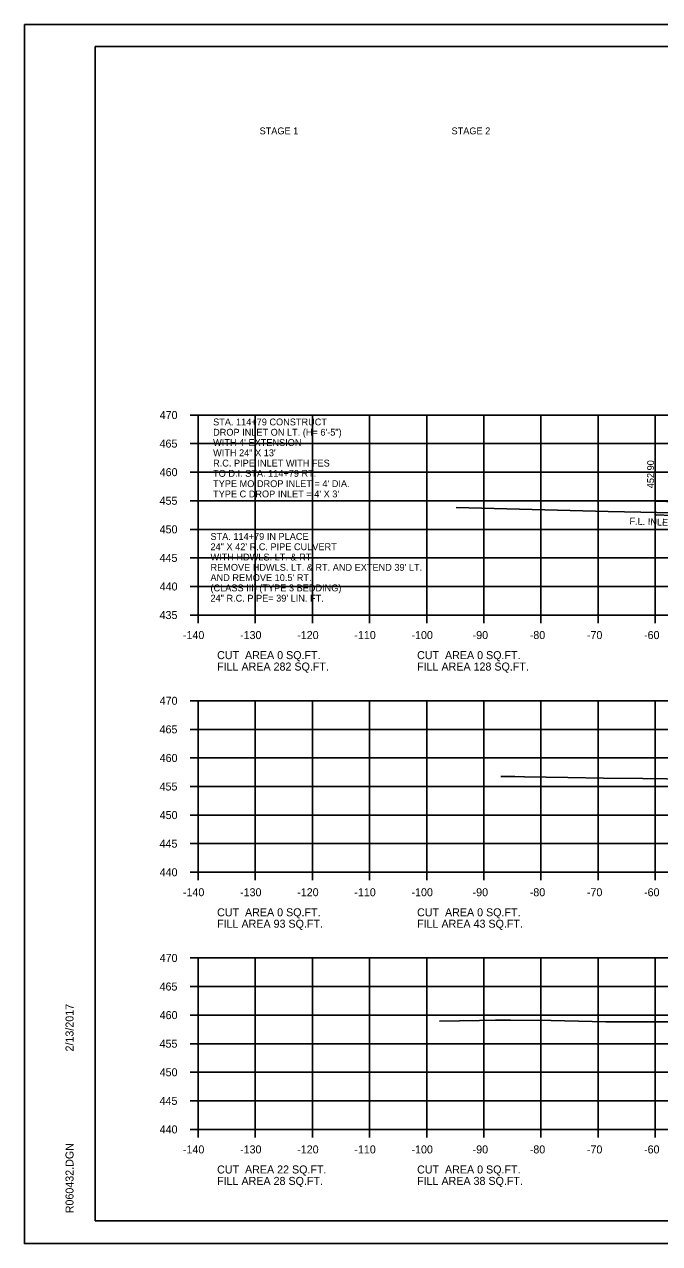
# Model space of a CAD drawing. Extents: x 1538688 to 1540766, y 656250 to 671912.
# Drawn here: x 1538687.8 to 1538798.9, y 658471.3 to 658684.6 of the extents above; entities that cross this region are included whole.
import ezdxf

# ---------------------------------------------------------------- set-up
doc = ezdxf.new("R2010")
doc.units = 0
for name, color, linetype in [('18', 7, 'Continuous'), ('22', 7, 'Continuous'), ('26', 7, 'Continuous'), ('40', 7, 'Continuous'), ('41', 7, 'Continuous'), ('Borings', 7, 'Continuous'), ('Default', 7, 'Continuous'), ('Horizontal Alignment', 7, 'Continuous'), ('RipRap', 7, 'Continuous')]:
    doc.layers.add(name, color=color, linetype=linetype)

msp = doc.modelspace()

# ---------------------------------------------------------------- linework, layer by layer
at = {"layer": '18'}
for points in [[(1538763.34, 658600.06), (1538789.92, 658599.36), (1538815.53, 658598.84)], [(1538771.17, 658553), (1538773.59, 658553.01), (1538775.27, 658552.94), (1538782.89, 658552.83), (1538789.15, 658552.74), (1538795.98, 658552.64), (1538804.31, 658552.52)], [(1538760.4, 658510.18), (1538767.42, 658510.32), (1538770.22, 658510.4), (1538771.41, 658510.38), (1538772.82, 658510.38), (1538779.98, 658510.31), (1538789.55, 658510.1), (1538793.35, 658510.1), (1538804.24, 658510.09)]]:
    msp.add_lwpolyline(points, dxfattribs=at)
at = {"layer": '22'}
for p, q in [((1538718.18, 658616.26), (1538998.18, 658616.26)), ((1538718.18, 658581.26), (1538718.18, 658616.26)), ((1538728.18, 658581.26), (1538728.18, 658616.26)), ((1538738.18, 658581.26), (1538738.18, 658616.26)), ((1538748.18, 658581.26), (1538748.18, 658616.26)), ((1538758.18, 658581.26), (1538758.18, 658616.26)), ((1538768.18, 658581.26), (1538768.18, 658616.26)), ((1538778.18, 658581.26), (1538778.18, 658616.26)), ((1538788.18, 658581.26), (1538788.18, 658616.26)), ((1538798.18, 658581.26), (1538798.18, 658616.26)), ((1538718.18, 658611.26), (1538998.18, 658611.26)), ((1538718.18, 658606.26), (1538998.18, 658606.26)), ((1538718.18, 658601.26), (1538998.18, 658601.26)), ((1538718.18, 658596.26), (1538998.18, 658596.26)), ((1538718.18, 658591.26), (1538998.18, 658591.26)), ((1538718.18, 658586.26), (1538998.18, 658586.26)), ((1538718.18, 658581.26), (1538998.18, 658581.26)), ((1538718.18, 658566.26), (1538998.18, 658566.26)), ((1538718.18, 658536.26), (1538718.18, 658566.26)), ((1538728.18, 658536.26), (1538728.18, 658566.26)), ((1538738.18, 658536.26), (1538738.18, 658566.26)), ((1538748.18, 658536.26), (1538748.18, 658566.26)), ((1538758.18, 658536.26), (1538758.18, 658566.26)), ((1538768.18, 658536.26), (1538768.18, 658566.26)), ((1538778.18, 658536.26), (1538778.18, 658566.26)), ((1538788.18, 658536.26), (1538788.18, 658566.26)), ((1538798.18, 658536.26), (1538798.18, 658566.26)), ((1538718.18, 658561.26), (1538998.18, 658561.26)), ((1538718.18, 658556.26), (1538998.18, 658556.26)), ((1538718.18, 658551.26), (1538998.18, 658551.26)), ((1538718.18, 658546.26), (1538998.18, 658546.26)), ((1538718.18, 658541.26), (1538998.18, 658541.26)), ((1538718.18, 658536.26), (1538998.18, 658536.26)), ((1538718.18, 658521.26), (1538998.18, 658521.26)), ((1538718.18, 658491.26), (1538718.18, 658521.26)), ((1538728.18, 658491.26), (1538728.18, 658521.26)), ((1538738.18, 658491.26), (1538738.18, 658521.26)), ((1538748.18, 658491.26), (1538748.18, 658521.26)), ((1538758.18, 658491.26), (1538758.18, 658521.26)), ((1538768.18, 658491.26), (1538768.18, 658521.26)), ((1538778.18, 658491.26), (1538778.18, 658521.26)), ((1538788.18, 658491.26), (1538788.18, 658521.26)), ((1538798.18, 658491.26), (1538798.18, 658521.26)), ((1538718.18, 658516.26), (1538998.18, 658516.26)), ((1538718.18, 658511.26), (1538998.18, 658511.26)), ((1538718.18, 658506.26), (1538998.18, 658506.26)), ((1538718.18, 658501.26), (1538998.18, 658501.26)), ((1538718.18, 658496.26), (1538998.18, 658496.26)), ((1538718.18, 658491.26), (1538998.18, 658491.26))]:
    msp.add_line(p, q, dxfattribs=at)
at = {"layer": '26'}
for p, q in [((1538687.78, 658684.61), (1539021.11, 658684.61)), ((1538798.32, 658601.21), (1538820.68, 658600.39)), ((1538798.32, 658598.79), (1538820.68, 658597.97)), ((1538687.78, 658471.28), (1539021.11, 658471.28))]:
    msp.add_line(p, q, dxfattribs=at)
msp.add_lwpolyline([(1538687.77, 658684.61), (1539021.11, 658684.61), (1539021.11, 658471.28), (1538687.77, 658471.28)], close=True, dxfattribs=at)
at = {"layer": 'Borings'}
for p, q in [((1538716.78, 658616.26), (1538718.18, 658616.26)), ((1538718.18, 658581.26), (1538718.18, 658616.26)), ((1538716.78, 658611.26), (1538718.18, 658611.26)), ((1538716.78, 658606.26), (1538718.18, 658606.26)), ((1538716.78, 658601.26), (1538718.18, 658601.26)), ((1538716.78, 658596.26), (1538718.18, 658596.26)), ((1538716.78, 658591.26), (1538718.18, 658591.26)), ((1538716.78, 658586.26), (1538718.18, 658586.26)), ((1538716.78, 658581.26), (1538718.18, 658581.26)), ((1538718.18, 658581.26), (1538998.18, 658581.26)), ((1538718.18, 658579.86), (1538718.18, 658581.26)), ((1538728.18, 658579.86), (1538728.18, 658581.26)), ((1538738.18, 658579.86), (1538738.18, 658581.26)), ((1538748.18, 658579.86), (1538748.18, 658581.26)), ((1538758.18, 658579.86), (1538758.18, 658581.26)), ((1538768.18, 658579.86), (1538768.18, 658581.26)), ((1538778.18, 658579.86), (1538778.18, 658581.26)), ((1538788.18, 658579.86), (1538788.18, 658581.26)), ((1538798.18, 658579.86), (1538798.18, 658581.26)), ((1538716.78, 658566.26), (1538718.18, 658566.26)), ((1538718.18, 658536.26), (1538718.18, 658566.26)), ((1538716.78, 658561.26), (1538718.18, 658561.26)), ((1538716.78, 658556.26), (1538718.18, 658556.26)), ((1538716.78, 658551.26), (1538718.18, 658551.26)), ((1538716.78, 658546.26), (1538718.18, 658546.26)), ((1538716.78, 658541.26), (1538718.18, 658541.26)), ((1538716.78, 658536.26), (1538718.18, 658536.26)), ((1538718.18, 658536.26), (1538998.18, 658536.26)), ((1538718.18, 658534.86), (1538718.18, 658536.26)), ((1538728.18, 658534.86), (1538728.18, 658536.26)), ((1538738.18, 658534.86), (1538738.18, 658536.26)), ((1538748.18, 658534.86), (1538748.18, 658536.26)), ((1538758.18, 658534.86), (1538758.18, 658536.26)), ((1538768.18, 658534.86), (1538768.18, 658536.26)), ((1538778.18, 658534.86), (1538778.18, 658536.26)), ((1538788.18, 658534.86), (1538788.18, 658536.26)), ((1538798.18, 658534.86), (1538798.18, 658536.26)), ((1538716.78, 658521.26), (1538718.18, 658521.26)), ((1538718.18, 658491.26), (1538718.18, 658521.26)), ((1538716.78, 658516.26), (1538718.18, 658516.26)), ((1538716.78, 658511.26), (1538718.18, 658511.26)), ((1538716.78, 658506.26), (1538718.18, 658506.26)), ((1538716.78, 658501.26), (1538718.18, 658501.26)), ((1538716.78, 658496.26), (1538718.18, 658496.26)), ((1538716.78, 658491.26), (1538718.18, 658491.26)), ((1538718.18, 658491.26), (1538998.18, 658491.26)), ((1538718.18, 658489.86), (1538718.18, 658491.26)), ((1538728.18, 658489.86), (1538728.18, 658491.26)), ((1538738.18, 658489.86), (1538738.18, 658491.26)), ((1538748.18, 658489.86), (1538748.18, 658491.26)), ((1538758.18, 658489.86), (1538758.18, 658491.26)), ((1538768.18, 658489.86), (1538768.18, 658491.26)), ((1538778.18, 658489.86), (1538778.18, 658491.26)), ((1538788.18, 658489.86), (1538788.18, 658491.26)), ((1538798.18, 658489.86), (1538798.18, 658491.26))]:
    msp.add_line(p, q, dxfattribs=at)
at = {"layer": 'RipRap'}
for p, q in [((1538700.18, 658680.72), (1539016.36, 658680.72)), ((1538700.18, 658475.26), (1538700.18, 658680.72)), ((1538700.18, 658475.26), (1538700.18, 658475.26)), ((1539016.36, 658475.26), (1538700.18, 658475.26))]:
    msp.add_line(p, q, dxfattribs=at)

# ---------------------------------------------------------------- texts
at = {"layer": '40'}
for s, p in [('STA. 114+79 CONSTRUCT', (1538720.8, 658614.45)), ('DROP INLET ON LT. (H= 6\'-5") ', (1538720.8, 658612.65)), ("WITH 4' EXTENSION ", (1538720.8, 658610.85)), ('WITH 24" X 13\'', (1538720.8, 658609.05)), ('R.C. PIPE INLET WITH FES', (1538720.8, 658607.25)), ('TO D.I. STA. 114+79 RT.', (1538720.8, 658605.45)), ("TYPE MO DROP INLET = 4' DIA.", (1538720.8, 658603.65)), ("TYPE C DROP INLET = 4' X 3'", (1538720.8, 658601.85)), ('STA. 114+79 IN PLACE', (1538720.34, 658594.41)), ('24" X 42\' R.C. PIPE CULVERT', (1538720.34, 658592.61)), ('WITH HDWLS. LT. & RT.', (1538720.34, 658590.81)), ("AND REMOVE 10.5' RT.", (1538720.34, 658587.21)), ("REMOVE HDWLS. LT. & RT. AND EXTEND 39' LT.", (1538720.34, 658589.01)), ('(CLASS III) (TYPE 3 BEDDING)', (1538720.34, 658585.41)), ('24" R.C. PIPE= 39\' LIN. FT.', (1538720.34, 658583.61))]:
    msp.add_text(s, height=1.2, dxfattribs=at).set_placement(p)
msp.add_text('F.L. INLET=452.74', height=1.2, rotation=357.8986, dxfattribs=at).set_placement((1538793.65, 658597.12))
at = {"layer": '41'}
msp.add_text('452.90', height=1.2, rotation=90, dxfattribs=at).set_placement((1538797.96, 658603.45))
at = {"layer": 'Default'}
for s, p in [('STAGE 1', (1538728.93, 658665.38)), ('STAGE 2', (1538762.53, 658665.38))]:
    msp.add_text(s, height=1.2, dxfattribs=at).set_placement(p)
at = {"layer": 'Horizontal Alignment'}
for s, p in [('470', (1538711.45, 658615.56)), ('465', (1538711.43, 658610.56)), ('460', (1538711.45, 658605.56)), ('455', (1538711.43, 658600.56)), ('450', (1538711.45, 658595.56)), ('445', (1538711.43, 658590.56)), ('440', (1538711.45, 658585.56)), ('435', (1538711.43, 658580.56)), ('-140', (1538715.52, 658577.06)), ('-130', (1538725.52, 658577.06)), ('-120', (1538735.52, 658577.06)), ('-110', (1538745.52, 658577.06)), ('-100', (1538755.52, 658577.06)), ('-90', (1538766.22, 658577.06)), ('-80', (1538776.22, 658577.06)), ('-70', (1538786.22, 658577.06)), ('-60', (1538796.22, 658577.06)), ('CUT  AREA 0 SQ.FT.', (1538721.5, 658573.55)), ('CUT  AREA 0 SQ.FT.', (1538756.5, 658573.55)), ('FILL AREA 282 SQ.FT.', (1538721.5, 658571.55)), ('FILL AREA 128 SQ.FT.', (1538756.5, 658571.55)), ('470', (1538711.45, 658565.56)), ('465', (1538711.43, 658560.56)), ('460', (1538711.45, 658555.56)), ('455', (1538711.43, 658550.56)), ('450', (1538711.45, 658545.56)), ('445', (1538711.43, 658540.56)), ('440', (1538711.45, 658535.56)), ('-140', (1538715.52, 658532.06)), ('-130', (1538725.52, 658532.06)), ('-120', (1538735.52, 658532.06)), ('-110', (1538745.52, 658532.06)), ('-100', (1538755.52, 658532.06)), ('-90', (1538766.22, 658532.06)), ('-80', (1538776.22, 658532.06)), ('-70', (1538786.22, 658532.06)), ('-60', (1538796.22, 658532.06)), ('CUT  AREA 0 SQ.FT.', (1538721.5, 658528.55)), ('CUT  AREA 0 SQ.FT.', (1538756.5, 658528.55)), ('FILL AREA 93 SQ.FT.', (1538721.5, 658526.55)), ('FILL AREA 43 SQ.FT.', (1538756.5, 658526.55)), ('470', (1538711.45, 658520.56)), ('465', (1538711.43, 658515.56)), ('460', (1538711.45, 658510.56)), ('455', (1538711.43, 658505.56)), ('450', (1538711.45, 658500.56)), ('445', (1538711.43, 658495.56)), ('440', (1538711.45, 658490.56)), ('-140', (1538715.52, 658487.06)), ('-130', (1538725.52, 658487.06)), ('-120', (1538735.52, 658487.06)), ('-110', (1538745.52, 658487.06)), ('-100', (1538755.52, 658487.06)), ('-90', (1538766.22, 658487.06)), ('-80', (1538776.22, 658487.06)), ('-70', (1538786.22, 658487.06)), ('-60', (1538796.22, 658487.06)), ('CUT  AREA 22 SQ.FT.', (1538721.5, 658483.55)), ('CUT  AREA 0 SQ.FT.', (1538756.5, 658483.55)), ('FILL AREA 28 SQ.FT.', (1538721.5, 658481.55)), ('FILL AREA 38 SQ.FT.', (1538756.5, 658481.55))]:
    msp.add_text(s, height=1.4, dxfattribs=at).set_placement(p)
at = {"layer": 'RipRap'}
for s, p in [('2/13/2017', (1538696.37, 658504.9)), ('R060432.DGN', (1538696.37, 658476.59))]:
    msp.add_text(s, height=1.4, rotation=90, dxfattribs=at).set_placement(p)

doc.saveas('drawing.dxf')
